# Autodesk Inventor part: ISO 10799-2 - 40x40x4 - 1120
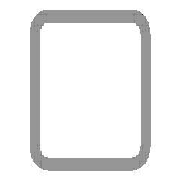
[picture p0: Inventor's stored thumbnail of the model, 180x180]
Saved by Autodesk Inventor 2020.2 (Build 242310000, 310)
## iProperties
Created: 2020-01
Part Number: ISO 10799-2 - 40x40x4 - 1120
Material: Steel, Mild
Description: Structural steels - Cold-formed, welded, structural hollow sections
Document SubType Name: Modeling
Standard: ISO
Designer: thira
Standard Revision: First edition 2011-09-15
Standards Organization: ISO
Language: en-US
Size Designation: 40x40x4
Categories: <MemberInstance><Categories><Category DisplayName="Structural Shapes" InternalName="089c4875-fa83-4c05-b084-43b9cc11f5ed" Mnemonic="GRDR"><CategoryParameter Dis
Stock Number: 40x40x4
Density: 7.85 g/cm^3
Appearance: Semi-Polished
_CCFamilyMember: 11
_CCFamilyDisplayName: ISO 10799-2 (Square) - Structural steels - Cold-formed, welded, structural hollow sections
_FrameMemberDoc: Frame Member File
_Version: 15.0.0
_GetPNFromCC: 1
G_L: 1120.000 mm
G_W: 40.000 mm
G_H: 40.000 mm
IsCustomPart: 1
Author: thira
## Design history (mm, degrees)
node "Start Plane"
node "End Plane"
sketch "Sketch"
  geometry: L1 (-20, -12)-(-20, 12); L2 (-12, 20)-(12, 20); L3 (20, 12)-(20, -12); L4 (12, -20)-(-12, -20); L5 (-12, 16)-(12, 16); L6 (16, 12)-(16, -12); L7 (12, -16)-(-12, -16); L8 (-16, -12)-(-16, 12); L9 (0, 30.32)-(0, -30.32) reference; L10 (-30.32, 0)-(30.32, 0) reference; A1 r 8 centre (-12, -12) between (-20, -12) and (-12, -20); A2 r 8 centre (12, 12) between (20, 12) and (12, 20); A3 r 8 centre (-12, 12) between (-12, 20) and (-20, 12); A4 r 8 centre (12, -12) between (12, -20) and (20, -12); A5 r 4 centre (-12, 12) between (-12, 16) and (-16, 12); A6 r 4 centre (12, 12) between (16, 12) and (12, 16); A7 r 4 centre (12, -12) between (12, -16) and (16, -12); A8 r 4 centre (-12, -12) between (-16, -12) and (-12, -16)
  constraints: 16 end point, 16 point on circle, 8 centre point, 8 tangent, 4 parallel, 3 equal radius, 2 perpendicular, 7 other
  dimensions: "d7" = 8 radius of A1 (= G_IR); "d9" = 40 distance between parallel lines of L1 L3 (= G_W); "d11" = 40 distance between parallel lines of L2 L4 (= G_H); "d12" = 4 distance between parallel lines of L3 L6 (= G_T); "d15" = 20 distance between parallel lines of L9 L3 (= 0.5 x d9); "d16" = 20 distance between parallel lines of L2 L10 (= 0.5 x d11)
extrude "Body" new body sketch "Sketch" stored distance "d3" = 1120 (= G_L); taper "d4" = 0 deg
node "Driven Length"
  sketch "Sketch3"
    geometry: L1 (0, 0)-(10, 0) reference
    constraints: 2 end point, 1 horizontal
  workplane "Work Plane3"
  sketch "Sketch4"
    geometry: L1 (-2, 40)-(12, 40) reference; L2 (-2, 1160)-(12, 1160) reference
    dimensions: "d18" = 1120 distance between parallel lines of L1 L2 (derived)
workplane "Work Plane4"
split "Split1"
workplane "Work Plane5"
split "Split2"
body "Solid1"
other parameters: "G_W" = 40 [user parameter; used in 1 equation term], "G_H" = 40 [user parameter; used in 1 equation term], "G_T" = 4 [user parameter; used in 1 equation term], "G_IR" = 8 [user parameter; used in 1 equation term], "G_L" = 1120 (= d18) [user parameter; used in 1 equation term], "d17" = 90 deg, "MAS" = 0.42 [user parameter]
